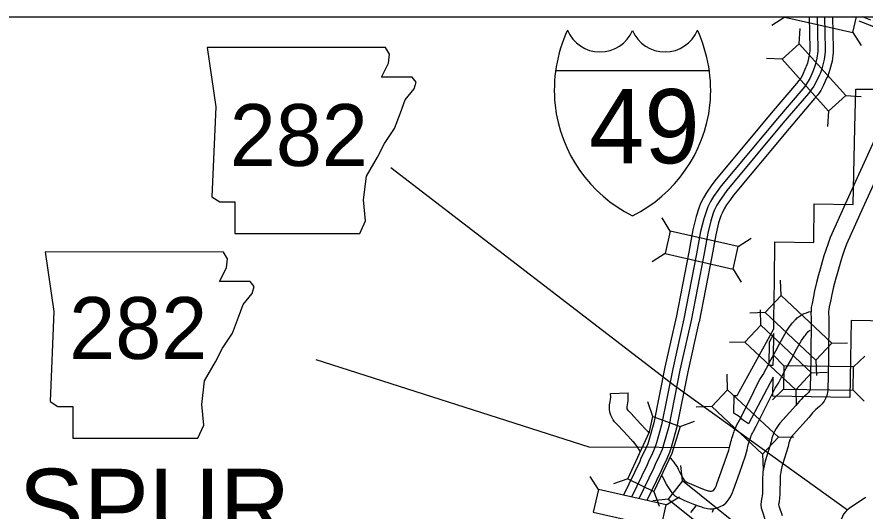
# Model space of a CAD drawing. Extents: x 535214 to 694517, y 381272 to 484355.
# Drawn here: x 552423 to 559659, y 476004 to 480223 of the extents above; entities that cross this region are included whole.
import ezdxf

# ---------------------------------------------------------------- set-up
doc = ezdxf.new("R2010")
doc.units = 0
for name, color, linetype in [('1', 7, 'Continuous'), ('Level 10', 7, 'Continuous'), ('Level 11', 7, 'Continuous'), ('Level 15', 7, 'Continuous'), ('Level 19', 7, 'Continuous'), ('Level 20', 7, 'Continuous'), ('Level 21', 7, 'Continuous'), ('Level 23', 7, 'Continuous'), ('Level 6', 7, 'Continuous')]:
    doc.layers.add(name, color=color, linetype=linetype)

msp = doc.modelspace()

# ---------------------------------------------------------------- linework, layer by layer
at = {"layer": '1'}
msp.add_lwpolyline([(535213.7, 480223.3), (566227, 480223.3), (566227, 448175.2), (535213.7, 448175.2)], close=True, dxfattribs=at)
at = {"layer": 'Level 10'}
msp.add_line((557487.9, 477006.3), (557637.7, 477013.1), dxfattribs=at)
for points in [[(558542.7, 476685.4), (558549.8, 476705), (558555.6, 476717.5), (558561.8, 476733.9), (558576.1, 476758.8), (558598.6, 476799.2), (558709.7, 477024.8), (558731.8, 477066.4), (558762.8, 477126), (558789.8, 477170.9), (558818.2, 477222.9), (558854.6, 477293.8), (558899.1, 477372.7), (558931.4, 477436.4), (558990.1, 477539.6), (559006.9, 477564.6), (559021.4, 477584.9), (559032.8, 477600.6), (559041.6, 477610.6), (559046.8, 477617.2), (559054.8, 477626.3), (559058.7, 477630.3), (559063.2, 477635.5), (559067.7, 477640.5), (559079.6, 477652.9), (559096.8, 477664.8), (559104.5, 477670.5), (559121.1, 477681.1), (559139.1, 477690.4), (559159, 477697.7), (559178.9, 477704.2), (559197.3, 477708.8)], [(558683.6, 476633.9), (558688.7, 476648), (558694, 476659.7), (558697.8, 476669.5), (558706.7, 476685), (558731.5, 476729.5), (558843.3, 476956.5), (558864.6, 476996.6), (558893.7, 477052.6), (558919.9, 477096.2), (558950.8, 477152.7), (558986.7, 477222.7), (559031.4, 477301.9), (559063.6, 477365.4), (559117.8, 477460.7), (559130.2, 477479.2), (559142.9, 477497), (559150, 477506.6), (559157.3, 477514.9), (559162.4, 477521.5), (559165.1, 477524.6), (559169.1, 477528.7), (559175.3, 477535.8), (559177.5, 477538.2), (559183.9, 477542.7), (559189.5, 477546.8), (559191.2, 477547.9)], [(557681.3, 476595.9), (557634.3, 476646.7), (557552.1, 476735.2), (557533.2, 476754.1), (557522.8, 476766.2), (557510.7, 476782.1), (557501.6, 476799), (557490.2, 476822.4), (557482.5, 476847.7), (557479.7, 476869.8), (557479.2, 476891.8), (557479.9, 476911.5), (557485.1, 476936.9), (557488.1, 476959.1), (557489.2, 476977.4), (557487.9, 477006.3)], [(557791.4, 476697.8), (557744.3, 476748.7), (557660.1, 476839.3), (557643.2, 476856.3), (557639.4, 476860.6), (557637.3, 476863.4), (557635.2, 476867.4), (557630.2, 476877.6), (557629.7, 476879.1), (557629.5, 476880.9), (557629.3, 476891), (557629.4, 476893.7), (557633.1, 476911.6), (557637.5, 476944.6), (557639.4, 476976.3), (557637.7, 477013.1)], [(557794.7, 476694), (557804.6, 476681.8), (557814.5, 476668.5)], [(557996.9, 476456.9), (557999.7, 476454.1), (558010.6, 476441.4), (558025.9, 476423.3), (558036.7, 476408.1), (558047.9, 476391.5), (558058.1, 476374.9), (558065.3, 476361.4), (558077.5, 476338.1), (558088.4, 476316.8), (558095.1, 476305), (558101.3, 476293.2), (558108.7, 476280.9), (558116.7, 476268.6), (558123.1, 476259.8), (558125.9, 476257.2), (558134.6, 476253.1), (558144.3, 476248.5), (558178, 476232.6), (558259.5, 476199.4), (558295.5, 476186.2), (558311.4, 476180.6), (558320.8, 476177.4), (558326.3, 476175.8), (558334.2, 476174), (558334.2, 476174), (558339.1, 476173.7), (558345.6, 476173.8), (558350.4, 476174.2), (558357.2, 476176.1), (558364.3, 476178.9), (558366.6, 476180), (558366.9, 476180.3), (558372.8, 476189), (558379.5, 476199.9), (558390.5, 476221.4), (558395.4, 476234.8), (558445.4, 476377.1), (558495.9, 476522.6), (558502.7, 476545.3), (558506.8, 476561.8), (558511.2, 476580.2), (558514.6, 476593.9), (558518.9, 476608.6), (558523.3, 476624.8), (558527.2, 476639.4), (558532.8, 476656.7), (558537.7, 476669.6), (558541.5, 476682)], [(557678.1, 476599.6), (557686.3, 476589.6), (557700.7, 476570.3), (557714.5, 476550.9), (557726.7, 476532.7), (557741.7, 476509.5)], [(557923, 476308.2), (557928, 476300.1), (557932.7, 476291.3), (557944.3, 476269.1), (557956.3, 476245.8), (557963.5, 476232.9), (557970.7, 476219.4), (557981.4, 476201.5), (557993, 476183.7), (558010.2, 476160), (558037.2, 476134.8), (558057.1, 476123.7), (558070.5, 476117.5), (558080, 476112.9), (558117.8, 476095.2), (558205.4, 476059.5), (558244.8, 476045), (558262.6, 476038.8), (558275.8, 476034.3), (558287.8, 476030.8), (558303.5, 476027.1), (558316, 476024.8), (558335.7, 476023.6), (558353.6, 476023.9), (558377.2, 476026), (558405.2, 476033.7), (558424.4, 476041.4), (558448.3, 476052.8), (558470.5, 476071.4), (558484.3, 476086.3), (558498.7, 476107.3), (558510.4, 476126.3), (558528.3, 476161.3), (558536.6, 476184.1), (558587, 476327.7), (558638.7, 476476.5), (558647.4, 476505.6), (558652.5, 476526.2), (558656.9, 476544.5), (558659.5, 476554.9), (558663.2, 476567.8), (558668.1, 476585.4), (558671.2, 476596.9), (558674.5, 476607.3), (558679.6, 476621), (558684.7, 476637.3)]]:
    msp.add_lwpolyline(points, dxfattribs=at)
at = {"layer": 'Level 11'}
for points in [[(559667.1, 476119), (559637.8, 476101.3), (559584.4, 476065.9), (559535.4, 476033.2), (559509.2, 476013.4), (559495, 475999.7), (559475.9, 475978.2), (559465.9, 475956.7), (559441.7, 475900.8), (559357.9, 475694.1), (559343.2, 475660.2), (559334.5, 475644.6), (559314.6, 475605.8), (559213.5, 475428.9), (559207.8, 475421.5), (559205.9, 475419.9), (559201.7, 475417.1), (559186.8, 475411.6), (559179.5, 475409.4), (559164.1, 475408.1), (559038.6, 475411.3)], [(558218.5, 476057.8), (558216.4, 476047.3), (558205.3, 476033.5), (558194.5, 476021.5), (558183.5, 476008.8), (558171.2, 475990.3)], [(558365, 476025.4), (558361.4, 476007.7), (558356.1, 475990.6)]]:
    msp.add_lwpolyline(points, dxfattribs=at)
at = {"layer": 'Level 15'}
for points in [[(560019.4, 479785.2), (559504.8, 478654.4), (559362.8, 478338.8), (559340.9, 478281), (559323.8, 478232.2), (559308.7, 478183.5), (559294.2, 478130.6), (559276.7, 478070.4), (559262.2, 478019.8), (559245.2, 477955.2), (559227.9, 477885.7), (559218.8, 477835.2), (559207.2, 477775.9), (559200.9, 477743.1), (559198.5, 477717.3), (559198.2, 477691.9), (559199.3, 477651.1)], [(560156.1, 479723.4), (559641.4, 478592.6), (559501.4, 478281.5), (559481.9, 478229.7), (559466.3, 478185.1), (559452.7, 478141.4), (559438.6, 478089.9), (559420.8, 478028.7), (559406.8, 477979.9), (559390.5, 477918.1), (559374.7, 477854.2), (559366.2, 477807.4), (559354.4, 477747.4), (559349.6, 477722), (559348.4, 477709.7), (559348.3, 477693.1), (559349.3, 477655)], [(559199.3, 477653.7), (559196.3, 477313.3), (559192.5, 477046.6), (559190.9, 477038.8), (559187.6, 477031.7), (559183.4, 477023.8), (559177.8, 477016.2), (559170.8, 477009), (559157.2, 476997.6), (559142.9, 476986), (559130.6, 476975.7), (559113.5, 476957.5), (559098.9, 476941), (559068.5, 476905.4), (558933.1, 476754.4), (558916.8, 476733.4), (558900.2, 476709.3), (558886.8, 476683.7), (558877.6, 476664.8), (558871.9, 476648.5), (558864.6, 476625.4), (558857.9, 476594.2), (558809.5, 476438.4), (558804.9, 476417.4), (558797.5, 476389.6), (558792.6, 476364.9), (558788, 476339), (558786.3, 476317.2), (558784.9, 476287.6), (558783.7, 476155.4), (558782.1, 476131.8), (558779.1, 476118.8), (558773.3, 476087), (558771.4, 476057), (558773.6, 476031.1), (558781.1, 476005), (558807, 475924.6)], [(559349.3, 477652.4), (559346.3, 477311.6), (559342.3, 477030.2), (559334.4, 476991.8), (559322, 476964.8), (559310.5, 476943.5), (559292.5, 476918.9), (559272.9, 476898.9), (559252.7, 476881.9), (559238.4, 476870.3), (559233.8, 476866.4), (559224.3, 476856.4), (559212.2, 476842.7), (559181.4, 476806.6), (559048.3, 476658.2), (559037.9, 476644.9), (559028.9, 476631.8), (559020.7, 476616.1), (559016.2, 476606.9), (559014.2, 476601.1), (559009.8, 476587.1), (559003.1, 476556.1), (558954.7, 476400), (558950.7, 476381.9), (558943.7, 476355.6), (558940, 476337.2), (558937, 476320.1), (558936, 476307.8), (558934.9, 476283.4), (558933.7, 476149.5), (558930.9, 476110), (558926.2, 476088.9), (558922.5, 476068.6), (558921.8, 476058.6), (558921.8, 476058.5), (558924.6, 476048.7), (558951.1, 475966.5)]]:
    msp.add_lwpolyline(points, dxfattribs=at)
at = {"layer": 'Level 19'}
for points in [[(559182.6, 480223.3), (559187.9, 479951.2), (559187.7, 479933.7), (559181, 479882.8), (559168, 479829.5), (559157.7, 479799.3), (559151.5, 479787.9), (559125.2, 479727.5), (559110.9, 479701.2), (559095.7, 479679.4), (559074.7, 479653.5), (558859, 479400.6), (558376.8, 478822.5), (558347.2, 478780.5)], [(559251.4, 480223.3), (559256.7, 479951.4), (559256.4, 479928.8), (559248.7, 479870.2), (559234.1, 479810.2), (559220.9, 479771.7), (559213.4, 479757.8), (559187.1, 479697.4), (559169.5, 479665), (559150.7, 479638), (559127.6, 479609.6), (558911.5, 479356.3), (558431.4, 478780.6), (558403.4, 478740.9)], [(559313.9, 480223.3), (559319.2, 479951.6), (559318.8, 479924.2), (559310.2, 479858.7), (559294.1, 479792.6), (559278.4, 479746.5), (559269.6, 479730.3), (559243.3, 479670), (559222.8, 479632.1), (559200.6, 479600.4), (559175.7, 479569.6), (558959.3, 479316), (558481, 478742.5), (558454.5, 478704.9)], [(559382.6, 480223.3), (559387.9, 479951.8), (559387.5, 479919.3), (559377.9, 479846.1), (559360.2, 479773.4), (559341.6, 479718.8), (559331.5, 479700.2), (559305.1, 479639.8), (559281.4, 479595.9), (559255.6, 479559), (559228.5, 479525.6), (559011.8, 479271.7), (558535.6, 478700.7), (558510.7, 478665.4)], [(558347.6, 478781), (558309.6, 478727.8), (558280.2, 478678.6), (558256, 478629), (558241.1, 478591.7), (558217.6, 478519.3), (558189.5, 478405.7), (558154.7, 478213.5), (558046.8, 477656.9)], [(558403.5, 478741.1), (558367.2, 478690.1), (558340.7, 478645.8), (558318.9, 478601.2), (558305.8, 478568.3), (558283.8, 478500.4), (558256.7, 478391.3), (558222.3, 478200.8), (558114.3, 477643.8)], [(558454.4, 478704.8), (558419.5, 478655.9), (558395.7, 478616), (558376, 478575.8), (558364.6, 478547.1), (558343.9, 478483.3), (558317.9, 478378.2), (558283.7, 478189.3), (558175.7, 477632)], [(558510.4, 478664.9), (558477.1, 478618.2), (558456.2, 478583.2), (558439, 478548), (558429.3, 478523.7), (558410.1, 478464.4), (558385.1, 478363.8), (558351.3, 478176.7), (558243.2, 477618.9)], [(558047.5, 477660), (557950.9, 477233.7), (557856.9, 476756.5), (557815.3, 476607.1), (557805, 476577.1), (557783, 476527.5), (557747.6, 476454), (557736.6, 476426.8), (557598.9, 476138.4)], [(558114.5, 477644.8), (558018.2, 477219.4), (557923.8, 476740.7), (557881, 476586.7), (557869.1, 476551.9), (557845.4, 476498.6), (557810.5, 476426.1), (557799.5, 476399.1), (557667.6, 476122.8)], [(558175.5, 477631), (558079.3, 477206.5), (557984.7, 476726.2), (557940.7, 476568.2), (557927.3, 476529), (557902.1, 476472.3), (557867.6, 476400.8), (557856.7, 476373.8), (557730.1, 476108.6)], [(558242.5, 477615.8), (558146.6, 477192.3), (558051.6, 476710.3), (558006.4, 476547.8), (557991.3, 476503.8), (557964.5, 476443.4), (557930.5, 476372.9), (557919.6, 476346.1), (557798.8, 476093)]]:
    msp.add_lwpolyline(points, dxfattribs=at)
at = {"layer": 'Level 20'}
for p, q in [((558975.8, 480221.8), (558864.1, 480151.4)), ((559707.9, 480196.3), (559638.8, 480223.3)), ((559733.3, 480138.4), (559610.3, 480186.4)), ((559098.3, 479994.2), (559105.5, 480126)), ((559555, 480090.3), (559625.4, 479978.6)), ((558950.9, 479862), (558819.1, 479869.2)), ((559494.8, 479551.9), (559626.6, 479544.6)), ((559347.3, 479419.7), (559340.1, 479287.9)), ((557997.6, 478395.2), (557927.2, 478506.9)), ((558576.9, 478263.7), (558688.5, 478334.1)), ((557953.8, 478202.1), (557842.1, 478131.7)), ((558533, 478070.6), (558603.4, 477958.9)), ((558943.2, 477843.6), (558939, 477975.5)), ((558807.7, 477699.2), (558675.8, 477695)), ((558770.6, 477591.2), (558766.4, 477723.1)), ((558635.1, 477446.8), (558503.2, 477442.6)), ((559376.3, 477437.1), (559508.3, 477441.3)), ((558967.8, 477243.4), (558875.8, 477338.1)), ((559561.7, 477235), (559656.4, 477327)), ((559240.9, 477292.7), (559245, 477160.8)), ((558487.1, 477040.3), (558482.9, 477172.3)), ((559203.7, 477184.7), (559335.7, 477188.9)), ((558964.9, 477045.4), (558870.3, 476953.4)), ((559068.2, 477040.3), (559072.4, 476908.4)), ((559558.9, 477037), (559650.9, 476942.3)), ((557849.7, 476812), (557804.7, 476936.1)), ((558351.6, 476896), (558219.7, 476891.8)), ((557849.7, 476812), (558081.3, 476724.9)), ((558081.3, 476724.9), (558205.4, 476769.9)), ((558920.3, 476633.9), (559052.2, 476638)), ((558784.8, 476489.5), (558789, 476357.5)), ((558102.4, 476260.5), (558087.6, 476391.7)), ((557384.4, 476187.1), (557314, 476298.7)), ((557636.4, 476279.8), (557512.3, 476234.8)), ((557636.4, 476279.8), (557858.5, 476170.6)), ((557858.5, 476170.6), (557903.5, 476046.5)), ((557978.9, 476105.7), (557847.8, 476090.9)), ((557963.6, 476055.6), (558075.3, 476125.9))]:
    msp.add_line(p, q, dxfattribs=at)
for points in [[(558976.1, 480223.3), (558975.8, 480221.8), (559555, 480090.3), (559585.2, 480223.3)], [(557636.4, 476279.8), (557819.8, 476679.8), (557849.7, 476812)], [(558081.3, 476724.9), (558011.9, 476494.8), (557858.5, 476170.6)]]:
    msp.add_lwpolyline(points, dxfattribs=at)
for points in [[(558950.9, 479862), (559347.3, 479419.7), (559494.8, 479551.9), (559098.3, 479994.2)], [(557953.8, 478202.1), (558533, 478070.6), (558576.9, 478263.7), (557997.6, 478395.2)], [(559376.3, 477437.1), (558943.2, 477843.6), (558807.7, 477699.2), (559240.9, 477292.7)], [(559203.7, 477184.7), (558770.6, 477591.2), (558635.1, 477446.8), (559068.2, 477040.3)], [(559561.7, 477235), (558967.8, 477243.4), (558964.9, 477045.4), (559558.9, 477037)], [(558920.3, 476633.9), (558487.1, 477040.3), (558351.6, 476896), (558784.8, 476489.5)], [(557978.9, 476105.7), (558443.3, 475735.3), (558566.8, 475890.1), (558102.4, 476260.5)], [(557340.5, 475994), (557919.8, 475862.5), (557963.6, 476055.6), (557384.4, 476187.1)]]:
    msp.add_lwpolyline(points, close=True, dxfattribs=at)
at = {"layer": 'Level 21'}
for points in [[(554044.8, 479963.7), (554120.9, 479456.2), (554087.1, 478686.4), (554154.8, 478644.1), (554281.7, 478644.1), (554281.7, 478373.4), (555347.5, 478373.4), (555398.2, 478483.4), (555381.3, 478661), (555406.7, 478864), (555499.8, 479024.8), (555559, 479143.2), (555643.6, 479270.1), (555694.3, 479405.4), (555736.6, 479515.4), (555812.7, 479608.4), (555829.7, 479667.6), (555795.8, 479709.9), (555533.6, 479709.9), (555592.8, 479828.4), (555601.3, 479904.5), (555566.2, 479963)], [(552662.7, 478216.7), (552738.9, 477709.1), (552705, 476939.4), (552772.7, 476897.1), (552899.6, 476897.1), (552899.6, 476626.4), (553965.4, 476626.4), (554016.2, 476736.3), (553999.2, 476914), (554024.6, 477117), (554117.7, 477277.7), (554176.9, 477396.1), (554261.5, 477523), (554312.2, 477658.4), (554354.5, 477768.3), (554430.6, 477861.4), (554447.6, 477920.6), (554413.7, 477962.9), (554151.5, 477962.9), (554210.7, 478081.3), (554219.2, 478157.4), (554184.1, 478215.9)]]:
    msp.add_lwpolyline(points, close=True, dxfattribs=at)
for points in [[(555614.1, 478937.4), (558033.7, 477076.6), (559509.2, 476013.4)], [(554973.4, 477297), (557302.7, 476550.9), (558500.9, 476546.3)]]:
    msp.add_lwpolyline(points, dxfattribs=at)
at = {"layer": 'Level 23'}
msp.add_line((557019.6, 479766.1), (558330.5, 479766.1), dxfattribs=at)
for centre, radius, start, end in [((558237.8, 479595.3), 1230.1, 155.22044, 185.79282), ((557398.5, 480223.8), 299.7, 202.14594, 337.34139), ((557951.6, 480223.8), 299.7, 202.65861, 337.85406), ((557112.3, 479595.3), 1230.1, 354.20718, 24.77956), ((558215.2, 479605.7), 1208.7, 186.39228, 243.45705), ((557134.9, 479605.7), 1208.7, 296.54295, 353.60772)]:
    msp.add_arc(centre, radius, start, end, dxfattribs=at)
at = {"layer": 'Level 6'}
for points in [[(559559.1, 478622.4), (559572.9, 479279.2), (559579.8, 479607.6), (559746.5, 479605.2), (559753.5, 479933.7)], [(558890, 478302.6), (559221.6, 478297.3), (559226.7, 478627.5)], [(559226.7, 478627.5), (559559.1, 478622.4)], [(558880.4, 477560.4), (558881.4, 477642.4), (558885.7, 477972.5), (558890, 478302.6)], [(559871.4, 477625.8), (559541.4, 477631.4), (559535.5, 477301), (559530, 476972.4), (559200.8, 476978.4), (558871.5, 476984.3), (558874.3, 477148.3), (558664.9, 476748.2), (558622.8, 476777.4), (558609, 476788), (558599.4, 476799.7), (558592, 476805.5), (558575.5, 476817.2), (558563.9, 476824.6), (558551.7, 476831.5), (558539.6, 476840), (558542.2, 476990.2), (558567.2, 476989.7), (558880.4, 477560.4)], [(558879.8, 477520.2), (558840.9, 477447), (558837.4, 477249.3), (558876, 477248.6), (558877.1, 477312.3), (558879.8, 477520.2)]]:
    msp.add_lwpolyline(points, dxfattribs=at)

# ---------------------------------------------------------------- texts
at = {"layer": 'Level 21'}
for s, height, p in [('282', 528, (554239.3, 478950.7)), ('282', 528, (552868.8, 477302.8)), ('SPUR', 623.56, (552437, 475741.2))]:
    msp.add_text(s, height=height, dxfattribs=at).set_placement(p)
at = {"layer": 'Level 23'}
msp.add_text('49', height=633.6, dxfattribs=at).set_placement((557305.4, 478973.4))

doc.saveas('drawing.dxf')
